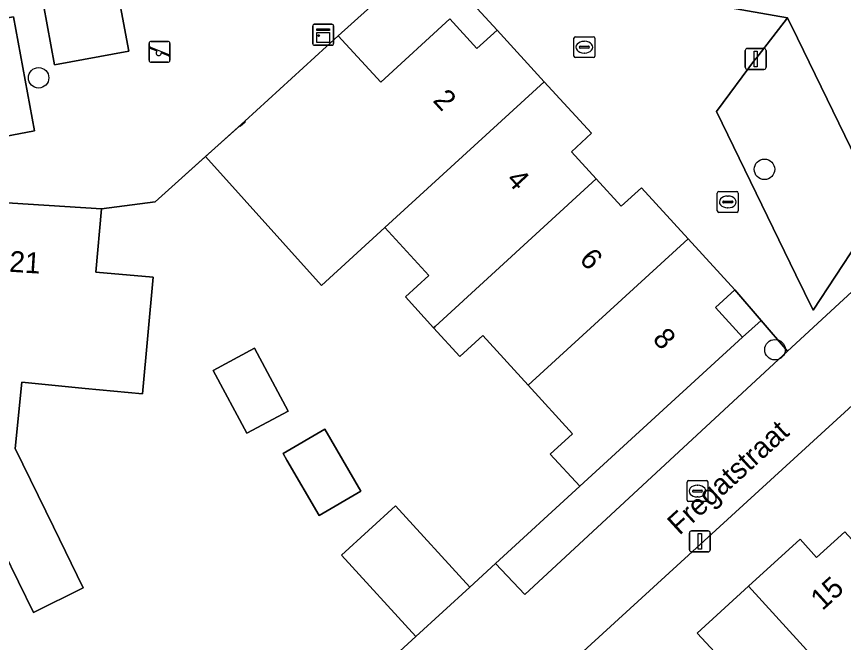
# Model space of a CAD drawing. Extents: x 159371 to 159986, y 382987 to 383597.
# Drawn here: x 159845.76 to 159885.28, y 383302.11 to 383332.01 of the extents above; entities that cross this region are included whole.
import ezdxf

# ---------------------------------------------------------------- set-up
doc = ezdxf.new("R2010")
doc.units = 0
for name, color, linetype in [('IMGEO_Boom', 7, 'Continuous'), ('IMGEO_Erf', 7, 'Continuous'), ('IMGEO_Kast', 7, 'Continuous'), ('IMGEO_Kolk', 7, 'Continuous'), ('IMGEO_Lichtmast', 7, 'Continuous'), ('IMGEO_Muur', 7, 'Continuous'), ('IMGEO_Openbare_ruimte_label', 7, 'Continuous'), ('IMGEO_Pand', 7, 'Continuous'), ('IMGEO_Pand_nummerreeks', 7, 'Continuous'), ('IMGEO_Parkeervlak_open', 7, 'Continuous'), ('IMGEO_Rijbaan_lokaal_open', 7, 'Continuous'), ('IMGEO_Speelvoorziening', 7, 'Continuous'), ('IMGEO_Terreindeel_open', 7, 'Continuous'), ('IMGEO_Voetpad_open', 7, 'Continuous')]:
    doc.layers.add(name, color=color, linetype=linetype)

msp = doc.modelspace()

# ---------------------------------------------------------------- linework, layer by layer
at = {"layer": 'IMGEO_Boom'}
for centre in [(159846.819, 383329.083), (159881.508, 383324.71), (159882.01, 383316.092)]:
    msp.add_circle(centre, 0.489, dxfattribs=at)
at = {"layer": 'IMGEO_Erf'}
for points in [[(159889.33, 383333.201), (159894.844, 383321.788), (159865.016, 383294.523), (159865.824, 383292.999), (159871.408, 383282.46), (159868.331, 383280.801), (159862.618, 383291.479), (159858.55, 383289.55), (159859.397, 383287.763), (159853.263, 383284.853), (159852.415, 383286.641), (159846.218, 383283.702), (159839.901, 383280.705)], [(159862.366, 383300.11), (159864.853, 383302.387), (159861.297, 383306.277), (159863.873, 383308.632), (159867.427, 383304.743), (159868.657, 383305.873), (159872.677, 383309.568), (159871.274, 383311.102), (159872.337, 383312.074), (159870.216, 383314.395), (159868.048, 383316.766), (159866.95, 383315.762), (159865.694, 383317.136), (159864.346, 383318.611), (159865.464, 383319.633), (159863.367, 383321.926), (159860.346, 383319.162), (159854.801, 383325.33), (159852.385, 383323.158), (159849.829, 383322.823), (159849.553, 383319.803), (159852.287, 383319.553), (159851.777, 383313.981), (159849.043, 383314.231), (159846.016, 383314.542), (159845.691, 383311.379), (159847.525, 383307.624), (159848.949, 383304.709), (159846.567, 383303.545), (159845.142, 383306.46)], [(159879.129, 383301.64), (159878.294, 383302.556), (159880.751, 383304.796), (159883.208, 383307.037), (159883.998, 383306.169), (159885.345, 383307.397)]]:
    msp.add_lwpolyline(points, dxfattribs=at)
for points in [[(159855.16, 383315.104), (159857.133, 383316.163), (159858.746, 383313.159), (159856.773, 383312.099)], [(159858.685, 383310.815), (159858.505, 383311.126), (159860.504, 383312.289), (159862.223, 383309.336), (159860.223, 383308.173)]]:
    msp.add_lwpolyline(points, close=True, dxfattribs=at)
at = {"layer": 'IMGEO_Kast'}
for p, q in [((159859.919, 383330.712), (159859.919, 383331.553)), ((159859.919, 383331.553), (159859.919, 383330.712)), ((159859.994, 383331.637), (159860.835, 383331.637)), ((159860.835, 383331.637), (159859.994, 383331.637)), ((159860.919, 383331.562), (159860.919, 383330.721)), ((159860.919, 383330.721), (159860.919, 383331.562)), ((159860.844, 383330.637), (159860.003, 383330.637)), ((159860.003, 383330.637), (159860.844, 383330.637))]:
    msp.add_line(p, q, dxfattribs=at)
for points in [[(159860.114, 383331.427), (159860.714, 383331.427), (159860.714, 383331.342), (159860.114, 383331.342), (159860.114, 383331.427)], [(159860.114, 383331.252), (159860.714, 383331.252), (159860.714, 383330.763), (159860.114, 383330.763), (159860.114, 383331.252)]]:
    msp.add_lwpolyline(points, dxfattribs=at)
msp.add_circle((159860.198, 383331.101), 0.0377, dxfattribs=at)
for centre, start, end in [((159859.997, 383331.559), 92.4484, 184.2845), ((159859.997, 383331.559), 92.4484, 184.2845), ((159860.841, 383331.559), 2.4484, 94.2845), ((159860.841, 383331.559), 2.4484, 94.2845), ((159859.997, 383330.715), 182.4484, 274.2845), ((159859.997, 383330.715), 182.4484, 274.2845), ((159860.841, 383330.715), 272.4484, 4.2845), ((159860.841, 383330.715), 272.4484, 4.2845)]:
    msp.add_arc(centre, 0.0779, start, end, dxfattribs=at)
at = {"layer": 'IMGEO_Kolk'}
for p, q in [((159872.399, 383330.119), (159872.399, 383330.971)), ((159872.474, 383331.045), (159873.326, 383331.045)), ((159872.887, 383330.825), (159872.912, 383330.825)), ((159873.4, 383330.971), (159873.4, 383330.119)), ((159872.658, 383330.539), (159872.658, 383330.551)), ((159873.096, 383330.502), (159872.698, 383330.502)), ((159872.701, 383330.588), (159873.099, 383330.588)), ((159873.142, 383330.551), (159873.142, 383330.539)), ((159873.326, 383330.045), (159872.474, 383330.045)), ((159872.91, 383330.265), (159872.885, 383330.265)), ((159879.254, 383322.726), (159879.254, 383323.578)), ((159879.329, 383323.652), (159880.181, 383323.652)), ((159880.255, 383323.578), (159880.255, 383322.726)), ((159879.513, 383323.146), (159879.513, 383323.158)), ((159879.556, 383323.195), (159879.954, 383323.195)), ((159879.742, 383323.432), (159879.767, 383323.432)), ((159879.997, 383323.158), (159879.997, 383323.146)), ((159879.951, 383323.109), (159879.553, 383323.109)), ((159879.765, 383322.872), (159879.74, 383322.872)), ((159880.181, 383322.652), (159879.329, 383322.652)), ((159877.808, 383308.91), (159877.808, 383309.762)), ((159877.883, 383309.836), (159878.735, 383309.836)), ((159878.809, 383309.762), (159878.809, 383308.91)), ((159878.067, 383309.33), (159878.067, 383309.342)), ((159878.11, 383309.379), (159878.508, 383309.379)), ((159878.296, 383309.616), (159878.321, 383309.616)), ((159878.551, 383309.342), (159878.551, 383309.33)), ((159878.505, 383309.293), (159878.107, 383309.293)), ((159878.319, 383309.056), (159878.294, 383309.056)), ((159878.735, 383308.836), (159877.883, 383308.836))]:
    msp.add_line(p, q, dxfattribs=at)
for points in [[(159872.399, 383330.119), (159872.399, 383330.971)], [(159872.474, 383331.045), (159873.326, 383331.045)], [(159873.4, 383330.971), (159873.4, 383330.119)], [(159873.326, 383330.045), (159872.474, 383330.045)], [(159879.254, 383322.726), (159879.254, 383323.578)], [(159879.329, 383323.652), (159880.181, 383323.652)], [(159880.255, 383323.578), (159880.255, 383322.726)], [(159880.181, 383322.652), (159879.329, 383322.652)], [(159877.808, 383308.91), (159877.808, 383309.762)], [(159877.883, 383309.836), (159878.735, 383309.836)], [(159878.809, 383309.762), (159878.809, 383308.91)], [(159878.735, 383308.836), (159877.883, 383308.836)]]:
    msp.add_lwpolyline(points, dxfattribs=at)
for centre, radius, start, end in [((159872.476, 383330.969), 0.0765, 91.552, 178.448), ((159872.476, 383330.969), 0.0765, 91.552, 178.448), ((159873.324, 383330.969), 0.0765, 1.552, 88.448), ((159873.324, 383330.969), 0.0765, 1.552, 88.448), ((159872.698, 383330.548), 0.0403, 85.8775, 175.7526), ((159872.695, 383330.538), 0.0366, 178.938, 274.7102), ((159873.099, 383330.545), 0.043, 264.8664, 352.4533), ((159873.103, 383330.55), 0.0386, 1.7309, 96.639), ((159872.476, 383330.121), 0.0765, 181.552, 268.448), ((159872.476, 383330.121), 0.0765, 181.552, 268.448), ((159873.324, 383330.121), 0.0765, 271.552, 358.448), ((159873.324, 383330.121), 0.0765, 271.552, 358.448), ((159879.331, 383323.576), 0.0765, 91.552, 178.448), ((159879.331, 383323.576), 0.0765, 91.552, 178.448), ((159880.179, 383323.576), 0.0765, 1.552, 88.448), ((159880.179, 383323.576), 0.0765, 1.552, 88.448), ((159879.553, 383323.155), 0.0403, 85.8775, 175.7526), ((159879.958, 383323.157), 0.0386, 1.7309, 96.639), ((159879.55, 383323.145), 0.0366, 178.938, 274.7102), ((159879.954, 383323.152), 0.043, 264.8664, 352.4533), ((159879.331, 383322.728), 0.0765, 181.552, 268.448), ((159879.331, 383322.728), 0.0765, 181.552, 268.448), ((159880.179, 383322.728), 0.0765, 271.552, 358.448), ((159880.179, 383322.728), 0.0765, 271.552, 358.448), ((159877.885, 383309.76), 0.0765, 91.552, 178.448), ((159877.885, 383309.76), 0.0765, 91.552, 178.448), ((159878.733, 383309.76), 0.0765, 1.552, 88.448), ((159878.733, 383309.76), 0.0765, 1.552, 88.448), ((159878.107, 383309.339), 0.0403, 85.8775, 175.7526), ((159878.104, 383309.329), 0.0366, 178.938, 274.7102), ((159878.508, 383309.336), 0.043, 264.8664, 352.4533), ((159878.512, 383309.341), 0.0386, 1.7309, 96.639), ((159877.885, 383308.912), 0.0765, 181.552, 268.448), ((159877.885, 383308.912), 0.0765, 181.552, 268.448), ((159878.733, 383308.912), 0.0765, 271.552, 358.448), ((159878.733, 383308.912), 0.0765, 271.552, 358.448)]:
    msp.add_arc(centre, radius, start, end, dxfattribs=at)
for centre, major_axis, ratio, start_param, end_param in [((159872.886, 383330.545), (-0.387, 0.002), 0.722429, 4.712389, 7.853982), ((159872.911, 383330.545), (-0.39, 0.002), 0.717154, 1.570796, 4.712389), ((159879.741, 383323.152), (-0.387, 0.002), 0.722429, 4.712389, 7.853982), ((159879.766, 383323.152), (-0.39, 0.002), 0.717154, 1.570796, 4.712389), ((159878.295, 383309.336), (-0.387, 0.002), 0.722429, 4.712389, 7.853982), ((159878.32, 383309.336), (-0.39, 0.002), 0.717154, 1.570796, 4.712389)]:
    msp.add_ellipse(centre, major_axis=major_axis, ratio=ratio, start_param=start_param, end_param=end_param, dxfattribs=at)
at = {"layer": 'IMGEO_Lichtmast'}
for p, q in [((159880.592, 383329.585), (159880.592, 383330.385)), ((159880.592, 383330.385), (159880.592, 383329.585)), ((159880.692, 383330.485), (159881.482, 383330.485)), ((159881.482, 383330.485), (159880.692, 383330.485)), ((159881.582, 383330.385), (159881.582, 383329.585)), ((159881.582, 383329.585), (159881.582, 383330.385)), ((159881.482, 383329.485), (159880.692, 383329.485)), ((159880.692, 383329.485), (159881.482, 383329.485)), ((159878.025, 383307.434), (159878.815, 383307.434)), ((159878.815, 383307.434), (159878.025, 383307.434)), ((159877.925, 383306.534), (159877.925, 383307.334)), ((159877.925, 383307.334), (159877.925, 383306.534)), ((159878.915, 383307.334), (159878.915, 383306.534)), ((159878.915, 383306.534), (159878.915, 383307.334)), ((159878.815, 383306.434), (159878.025, 383306.434)), ((159878.025, 383306.434), (159878.815, 383306.434))]:
    msp.add_line(p, q, dxfattribs=at)
for points in [[(159881.012, 383330.36), (159881.162, 383330.36), (159881.162, 383329.61), (159881.012, 383329.61), (159881.012, 383330.36)], [(159878.345, 383307.309), (159878.495, 383307.309), (159878.495, 383306.559), (159878.345, 383306.559), (159878.345, 383307.309)]]:
    msp.add_lwpolyline(points, dxfattribs=at)
for centre, start, end in [((159880.692, 383330.385), 90, 180), ((159880.692, 383330.385), 90, 180), ((159881.482, 383330.385), 0, 90), ((159881.482, 383330.385), 360, 90), ((159880.692, 383329.585), 180, 270), ((159880.692, 383329.585), 180, 270), ((159881.482, 383329.585), 270, 0), ((159881.482, 383329.585), 270, 0), ((159878.025, 383307.334), 90, 180), ((159878.025, 383307.334), 90, 180), ((159878.815, 383307.334), 0, 90), ((159878.815, 383307.334), 360, 90), ((159878.025, 383306.534), 180, 270), ((159878.025, 383306.534), 180, 270), ((159878.815, 383306.534), 270, 0), ((159878.815, 383306.534), 270, 0)]:
    msp.add_arc(centre, 0.1, start, end, dxfattribs=at)
at = {"layer": 'IMGEO_Muur'}
msp.add_lwpolyline([(159852.385, 383323.158), (159856.668, 383327.008)], dxfattribs=at)
at = {"layer": 'IMGEO_Pand'}
for points in [[(159870.985, 383328.895), (159868.729, 383331.362), (159867.766, 383330.482), (159866.475, 383331.894), (159863.167, 383328.87), (159861.135, 383331.093), (159856.668, 383327.008), (159856.695, 383326.978), (159856.457, 383326.764), (159856.43, 383326.794), (159854.801, 383325.33), (159860.346, 383319.162), (159863.367, 383321.926)], [(159863.367, 383321.926), (159865.464, 383319.633), (159864.346, 383318.611), (159865.694, 383317.136), (159865.765, 383317.208), (159873.471, 383324.249), (159872.279, 383325.553), (159873.239, 383326.43), (159870.985, 383328.895)], [(159873.471, 383324.249), (159865.765, 383317.208), (159865.694, 383317.136), (159866.95, 383315.762), (159868.048, 383316.766), (159870.216, 383314.395), (159877.866, 383321.393), (159875.636, 383323.832), (159874.664, 383322.944)], [(159852.287, 383319.553), (159849.553, 383319.803), (159849.829, 383322.823), (159842.806, 383323.274), (159841.879, 383313.138), (159843.085, 383310.669), (159844.096, 383308.601), (159845.142, 383306.46), (159846.567, 383303.545), (159848.949, 383304.709), (159847.525, 383307.624), (159845.691, 383311.379), (159846.016, 383314.542), (159849.043, 383314.231), (159851.777, 383313.981)], [(159877.866, 383321.393), (159870.216, 383314.395), (159872.337, 383312.074), (159871.274, 383311.102), (159872.677, 383309.568), (159880.463, 383316.686), (159879.166, 383318.104), (159880.096, 383318.954)], [(159855.16, 383315.104), (159856.773, 383312.099), (159858.746, 383313.159), (159857.133, 383316.163)], [(159858.685, 383310.815), (159860.223, 383308.173), (159862.223, 383309.336), (159860.504, 383312.289), (159858.505, 383311.126)], [(159864.853, 383302.387), (159867.427, 383304.743), (159863.873, 383308.632), (159861.297, 383306.277)], [(159887.615, 383297.266), (159889.84, 383299.294), (159890.891, 383298.141), (159892.475, 383299.585), (159885.345, 383307.397), (159883.998, 383306.169), (159883.208, 383307.037), (159880.751, 383304.796)], [(159877.837, 383300.461), (159884.919, 383292.704), (159886.23, 383293.899), (159885.182, 383295.048), (159887.615, 383297.266), (159880.751, 383304.796), (159878.294, 383302.556), (159879.129, 383301.64)]]:
    msp.add_lwpolyline(points, close=True, dxfattribs=at)
at = {"layer": 'IMGEO_Parkeervlak_open'}
msp.add_lwpolyline([(159883.082, 383330.981), (159882.613, 383331.946), (159881.088, 383329.987), (159881.087, 383329.985), (159879.214, 383327.479), (159883.012, 383319.671), (159883.831, 383317.987), (159887.034, 383322.854)], close=True, dxfattribs=at)
at = {"layer": 'IMGEO_Rijbaan_lokaal_open'}
msp.add_lwpolyline([(159882.174, 383337.602), (159881.859, 383337.661), (159881.768, 383337.219), (159869.905, 383339.262), (159869.058, 383334.343), (159882.613, 383331.946), (159883.082, 383330.981), (159887.034, 383322.854), (159887.954, 383320.962), (159882.61, 383316.018), (159870.056, 383304.404), (159868.657, 383305.873), (159867.427, 383304.743), (159864.853, 383302.387), (159862.366, 383300.11), (159865.016, 383294.523), (159894.844, 383321.788), (159889.33, 383333.201)], dxfattribs=at)
at = {"layer": 'IMGEO_Speelvoorziening'}
for p, q in [((159852.101, 383329.923), (159852.101, 383330.723)), ((159852.101, 383330.723), (159852.101, 383329.923)), ((159852.201, 383330.823), (159852.991, 383330.823)), ((159852.991, 383330.823), (159852.201, 383330.823)), ((159853.091, 383330.723), (159853.091, 383329.923)), ((159853.091, 383329.923), (159853.091, 383330.723)), ((159852.484, 383330.351), (159852.145, 383330.488)), ((159852.17, 383330.548), (159853.046, 383330.195)), ((159853.022, 383330.135), (159852.682, 383330.272)), ((159852.991, 383329.823), (159852.201, 383329.823)), ((159852.201, 383329.823), (159852.991, 383329.823))]:
    msp.add_line(p, q, dxfattribs=at)
for centre, radius, start, end in [((159852.201, 383330.723), 0.1, 90, 180), ((159852.201, 383330.723), 0.1, 90, 180), ((159852.991, 383330.723), 0.1, 0, 90), ((159852.991, 383330.723), 0.1, 360, 90), ((159852.158, 383330.518), 0.0327, 68.078, 248.078), ((159852.563, 383330.261), 0.12, 130.9928, 5.1632), ((159852.201, 383329.923), 0.1, 180, 270), ((159852.201, 383329.923), 0.1, 180, 270), ((159852.991, 383329.923), 0.1, 270, 0), ((159852.991, 383329.923), 0.1, 270, 0), ((159853.034, 383330.165), 0.0327, 248.078, 68.078)]:
    msp.add_arc(centre, radius, start, end, dxfattribs=at)
at = {"layer": 'IMGEO_Terreindeel_open'}
for points in [[(159849.383, 383337.048), (159846.728, 383336.623), (159847.327, 383333.661), (159846.88, 383333.542), (159847.584, 383329.707), (159851.136, 383330.348), (159850.379, 383334.359), (159849.93, 383334.294)], [(159845.624, 383331.992), (159843.576, 383331.639), (159842.69, 383331.161), (159843.692, 383325.989), (159846.625, 383326.547)]]:
    msp.add_lwpolyline(points, close=True, dxfattribs=at)
at = {"layer": 'IMGEO_Voetpad_open'}
for points in [[(159846.728, 383336.623), (159849.383, 383337.048), (159849.93, 383334.294), (159850.379, 383334.359), (159851.136, 383330.348), (159847.584, 383329.707), (159846.88, 383333.542), (159847.327, 383333.661)], [(159863.937, 383333.619), (159861.135, 383331.093), (159863.167, 383328.87), (159866.475, 383331.894), (159867.766, 383330.482), (159868.729, 383331.362), (159867.202, 383333.032)], [(159843.576, 383331.639), (159845.624, 383331.992), (159846.625, 383326.547), (159843.692, 383325.989), (159842.69, 383331.161)], [(159880.096, 383318.954), (159879.166, 383318.104), (159880.463, 383316.686), (159881.347, 383317.493)], [(159868.657, 383305.873), (159870.056, 383304.404), (159882.61, 383316.018), (159881.347, 383317.493), (159880.463, 383316.686), (159872.677, 383309.568)]]:
    msp.add_lwpolyline(points, close=True, dxfattribs=at)
for points in [[(159867.202, 383333.032), (159868.729, 383331.362), (159870.985, 383328.895), (159873.239, 383326.43), (159872.279, 383325.553), (159873.471, 383324.249), (159874.664, 383322.944), (159875.636, 383323.832), (159877.866, 383321.393), (159880.096, 383318.954), (159881.347, 383317.493), (159882.61, 383316.018), (159887.954, 383320.962), (159887.034, 383322.854), (159883.831, 383317.987), (159883.012, 383319.671), (159879.214, 383327.479), (159881.087, 383329.985), (159881.088, 383329.987), (159882.613, 383331.946), (159869.058, 383334.343)], [(159854.801, 383325.33), (159856.43, 383326.794), (159856.457, 383326.764), (159856.695, 383326.978), (159856.668, 383327.008), (159861.135, 383331.093), (159863.937, 383333.619)], [(159759.602, 383312.804), (159777.824, 383316.009), (159783.73, 383317.278), (159789.634, 383318.546), (159791.446, 383318.935), (159797.316, 383320.196), (159800.647, 383320.802), (159806.592, 383321.714), (159809.146, 383322.082), (159814.729, 383322.602), (159820.701, 383323.159), (159822.869, 383323.28), (159828.718, 383323.504), (159834.566, 383323.727), (159836.5, 383323.679), (159842.806, 383323.274), (159849.829, 383322.823), (159852.385, 383323.158), (159854.801, 383325.33)]]:
    msp.add_lwpolyline(points, dxfattribs=at)

# ---------------------------------------------------------------- texts
at = {"layer": 'IMGEO_Openbare_ruimte_label'}
msp.add_text('Fregatstraat', height=1, rotation=42.4471, dxfattribs=at).set_placement((159877.438, 383307.198))
at = {"layer": 'IMGEO_Pand_nummerreeks'}
for s, rotation, p in [('2', 312.6049, (159865.621, 383327.977)), ('4', 312.6072, (159869.12, 383324.174)), ('21', 356.3273, (159845.395, 383319.82)), ('6', 312.6072, (159872.617, 383320.372)), ('8', 312.6072, (159876.117, 383316.567)), ('15', 42.4226, (159884.277, 383303.598))]:
    msp.add_text(s, height=1, rotation=rotation, dxfattribs=at).set_placement(p)

doc.saveas('drawing.dxf')
